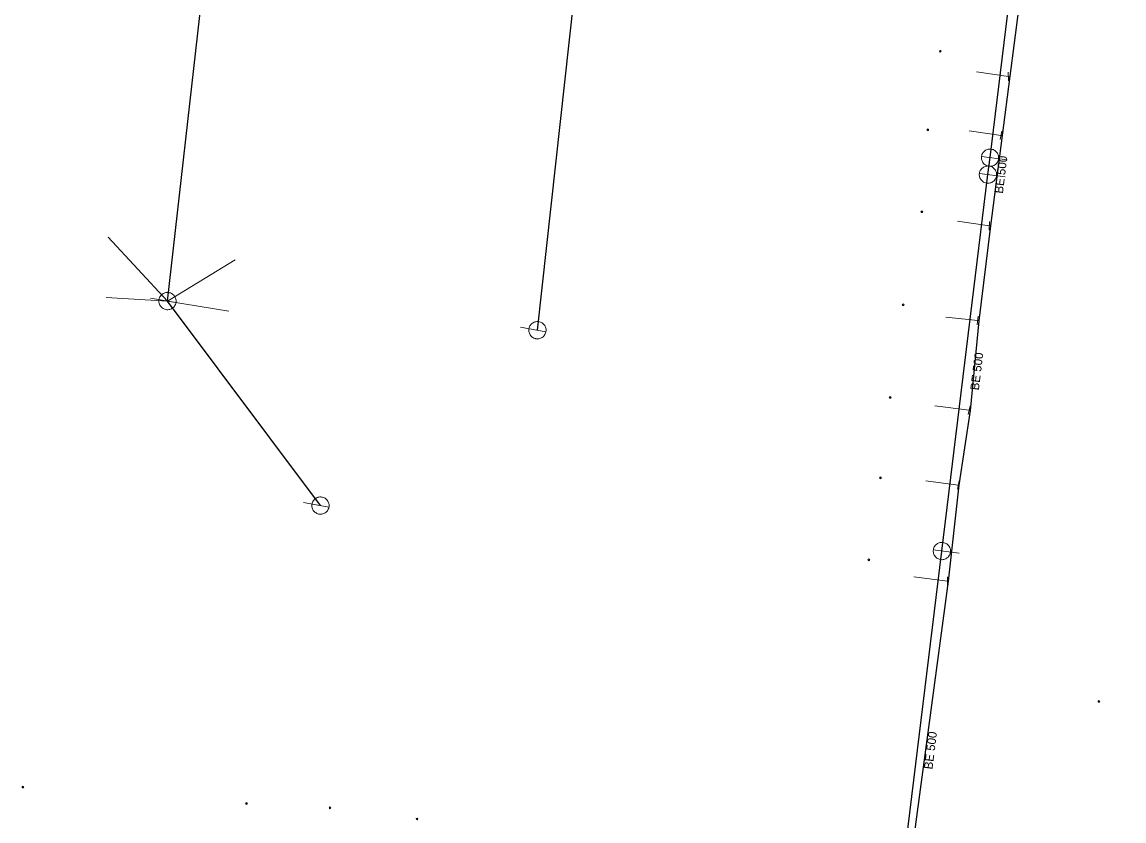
# Model space of a CAD drawing. Extents: x -783064 to -782702, y -1007904 to -1007145.
# Drawn here: x -783031.4 to -782903.8, y -1007381.8 to -1007289.3 of the extents above; entities that cross this region are included whole.
import ezdxf

# ---------------------------------------------------------------- set-up
doc = ezdxf.new("R2010")
doc.units = 0
doc.header["$LTSCALE"] = 0.4
doc.header["$PDMODE"] = 32
doc.header["$PDSIZE"] = 0.2
for name, color, linetype, lineweight in [('1', 7, 'Continuous', 13), ('11', 7, 'Continuous', 13), ('13', 7, 'Continuous', 13), ('14', 7, 'Continuous', 13), ('17', 7, 'Continuous', 25), ('22', 7, 'Continuous', 13), ('34', 7, 'Continuous', 13)]:
    doc.layers.add(name, color=color, linetype=linetype, lineweight=lineweight)

msp = doc.modelspace()

# ---------------------------------------------------------------- linework, layer by layer
at = {"layer": '1'}
for p in [(-782925.07, -1007292.719), (-782926.52, -1007301.809), (-782927.21, -1007311.299), (-782929.37, -1007322.069), (-782930.87, -1007332.779), (-782932, -1007342.089), (-782933.34, -1007351.579), (-782906.71, -1007367.969), (-783031.28, -1007377.879), (-783005.399, -1007379.789), (-782995.73, -1007380.279), (-782985.649, -1007381.569)]:
    msp.add_point(p, dxfattribs=at)
at = {"layer": '11'}
for p in [(-783021.414, -1007314.23), (-783006.703, -1007316.876), (-783021.626, -1007321.215), (-783007.444, -1007322.803)]:
    msp.add_line(p, (-783014.539, -1007321.63), dxfattribs=at)
at = {"layer": '13'}
for p, q in [((-782917.189, -1007295.627), (-782920.873, -1007295.112)), ((-782918.041, -1007302.452), (-782921.736, -1007301.928)), ((-782919.383, -1007312.937), (-782923.063, -1007312.385)), ((-782920.741, -1007323.879), (-782924.447, -1007323.499)), ((-782921.74, -1007334.257), (-782925.692, -1007333.773)), ((-782922.984, -1007342.927), (-782926.734, -1007342.418)), ((-782924.232, -1007354.049), (-782928.138, -1007353.554))]:
    msp.add_line(p, q, dxfattribs=at)
at = {"layer": '14', "lineweight": 25}
for p, q in [((-783014.539, -1007321.63), (-783008.89, -1007271.46)), ((-782971.71, -1007325), (-782966.579, -1007278.49)), ((-782996.829, -1007345.3), (-783014.539, -1007321.63))]:
    msp.add_line(p, q, dxfattribs=at)
at = {"layer": '14'}
for p, q in [((-782916.995, -1007295.62), (-782917.189, -1007295.627)), ((-782917.886, -1007302.487), (-782918.041, -1007302.452)), ((-782919.227, -1007312.942), (-782919.383, -1007312.937)), ((-782920.563, -1007323.904), (-782920.741, -1007323.879)), ((-782921.559, -1007334.301), (-782921.74, -1007334.257)), ((-782922.885, -1007342.946), (-782922.984, -1007342.927)), ((-782924.139, -1007354.049), (-782924.232, -1007354.049))]:
    msp.add_line(p, q, dxfattribs=at)
at = {"layer": '14', "lineweight": 25}
msp.add_lwpolyline([(-782930.292, -1007394.745), (-782924.885, -1007350.562), (-782919.554, -1007306.995), (-782919.314, -1007305.034), (-782912.27, -1007247.465)], dxfattribs=at)
at = {"layer": '17'}
msp.add_lwpolyline([(-782929.875, -1007401.245), (-782929.734, -1007399.601), (-782930.517, -1007396.682), (-782929.522, -1007392.415), (-782928.77, -1007388.515), (-782924.138, -1007354.049), (-782922.885, -1007342.946), (-782921.559, -1007334.301), (-782920.563, -1007323.904), (-782919.227, -1007312.942), (-782917.886, -1007302.487), (-782916.995, -1007295.62), (-782915.969, -1007287.894), (-782914.642, -1007276.256), (-782913.715, -1007269.301), (-782912.373, -1007257.698), (-782911.614, -1007250.289), (-782910.5, -1007239.254), (-782909.879, -1007233.809), (-782906.177, -1007206.061), (-782905.546, -1007203.154), (-782904.197, -1007194.592), (-782903.806, -1007194.072)], dxfattribs=at)
at = {"layer": '22'}
for p, q in [((-782917.328, -1007305.277), (-782920.306, -1007304.912)), ((-782917.568, -1007307.237), (-782920.546, -1007306.873)), ((-783016.509, -1007321.282), (-783013.554, -1007321.803)), ((-782973.68, -1007324.652), (-782970.725, -1007325.173)), ((-782998.799, -1007344.952), (-782995.844, -1007345.473)), ((-782922.899, -1007350.804), (-782925.877, -1007350.44))]:
    msp.add_line(p, q, dxfattribs=at)
for points in [[(-782919.192, -1007304.041), (-782919.3, -1007304.034), (-782919.41, -1007304.038), (-782919.519, -1007304.055), (-782919.624, -1007304.083), (-782919.726, -1007304.123), (-782919.823, -1007304.173), (-782919.914, -1007304.235), (-782919.998, -1007304.305), (-782920.074, -1007304.384), (-782920.14, -1007304.471), (-782920.197, -1007304.565), (-782920.242, -1007304.665), (-782920.277, -1007304.769), (-782920.3, -1007304.875), (-782920.311, -1007304.985), (-782920.311, -1007305.094), (-782920.299, -1007305.203), (-782920.275, -1007305.31), (-782920.238, -1007305.413), (-782920.192, -1007305.511), (-782920.134, -1007305.605), (-782920.066, -1007305.691), (-782919.989, -1007305.77), (-782919.905, -1007305.84), (-782919.814, -1007305.899), (-782919.716, -1007305.948), (-782919.613, -1007305.987), (-782919.508, -1007306.014), (-782919.399, -1007306.03), (-782919.289, -1007306.033), (-782919.18, -1007306.025), (-782919.073, -1007306.004), (-782918.968, -1007305.972), (-782918.868, -1007305.929), (-782918.772, -1007305.874), (-782918.684, -1007305.811), (-782918.602, -1007305.737), (-782918.53, -1007305.655), (-782918.466, -1007305.566), (-782918.413, -1007305.47), (-782918.371, -1007305.369), (-782918.34, -1007305.264), (-782918.321, -1007305.156), (-782918.313, -1007305.047), (-782918.318, -1007304.938), (-782918.334, -1007304.83), (-782918.362, -1007304.724), (-782918.402, -1007304.621), (-782918.453, -1007304.524), (-782918.513, -1007304.433), (-782918.583, -1007304.349), (-782918.663, -1007304.274), (-782918.749, -1007304.207), (-782918.843, -1007304.151), (-782918.942, -1007304.105), (-782919.047, -1007304.07), (-782919.154, -1007304.047)], [(-782919.432, -1007306.002), (-782919.54, -1007305.995), (-782919.65, -1007305.999), (-782919.759, -1007306.016), (-782919.864, -1007306.044), (-782919.966, -1007306.084), (-782920.063, -1007306.134), (-782920.154, -1007306.196), (-782920.238, -1007306.266), (-782920.314, -1007306.345), (-782920.38, -1007306.432), (-782920.437, -1007306.526), (-782920.482, -1007306.626), (-782920.517, -1007306.73), (-782920.54, -1007306.837), (-782920.551, -1007306.946), (-782920.551, -1007307.055), (-782920.539, -1007307.164), (-782920.515, -1007307.271), (-782920.478, -1007307.374), (-782920.432, -1007307.472), (-782920.373, -1007307.566), (-782920.306, -1007307.652), (-782920.229, -1007307.731), (-782920.145, -1007307.801), (-782920.054, -1007307.86), (-782919.956, -1007307.909), (-782919.853, -1007307.948), (-782919.748, -1007307.975), (-782919.639, -1007307.991), (-782919.529, -1007307.994), (-782919.42, -1007307.986), (-782919.313, -1007307.965), (-782919.208, -1007307.933), (-782919.107, -1007307.89), (-782919.012, -1007307.835), (-782918.924, -1007307.772), (-782918.842, -1007307.698), (-782918.77, -1007307.616), (-782918.706, -1007307.527), (-782918.653, -1007307.431), (-782918.611, -1007307.33), (-782918.58, -1007307.225), (-782918.561, -1007307.117), (-782918.553, -1007307.008), (-782918.558, -1007306.899), (-782918.574, -1007306.791), (-782918.602, -1007306.685), (-782918.642, -1007306.582), (-782918.693, -1007306.485), (-782918.753, -1007306.394), (-782918.823, -1007306.31), (-782918.903, -1007306.235), (-782918.989, -1007306.168), (-782919.083, -1007306.112), (-782919.182, -1007306.066), (-782919.287, -1007306.031), (-782919.394, -1007306.008)], [(-783014.713, -1007322.614), (-783014.604, -1007322.627), (-783014.495, -1007322.628), (-783014.385, -1007322.617), (-783014.279, -1007322.595), (-783014.174, -1007322.561), (-783014.075, -1007322.515), (-783013.981, -1007322.459), (-783013.894, -1007322.393), (-783013.814, -1007322.318), (-783013.743, -1007322.235), (-783013.681, -1007322.144), (-783013.631, -1007322.046), (-783013.59, -1007321.945), (-783013.562, -1007321.839), (-783013.544, -1007321.731), (-783013.539, -1007321.622), (-783013.546, -1007321.512), (-783013.564, -1007321.404), (-783013.595, -1007321.299), (-783013.636, -1007321.199), (-783013.689, -1007321.102), (-783013.752, -1007321.013), (-783013.825, -1007320.93), (-783013.905, -1007320.856), (-783013.993, -1007320.791), (-783014.088, -1007320.737), (-783014.189, -1007320.693), (-783014.293, -1007320.66), (-783014.401, -1007320.639), (-783014.51, -1007320.63), (-783014.619, -1007320.632), (-783014.727, -1007320.648), (-783014.834, -1007320.674), (-783014.937, -1007320.711), (-783015.035, -1007320.761), (-783015.126, -1007320.82), (-783015.212, -1007320.889), (-783015.288, -1007320.967), (-783015.356, -1007321.053), (-783015.414, -1007321.146), (-783015.462, -1007321.244), (-783015.499, -1007321.347), (-783015.524, -1007321.455), (-783015.537, -1007321.563), (-783015.538, -1007321.673), (-783015.527, -1007321.781), (-783015.505, -1007321.889), (-783015.47, -1007321.993), (-783015.425, -1007322.093), (-783015.369, -1007322.187), (-783015.304, -1007322.274), (-783015.228, -1007322.354), (-783015.145, -1007322.425), (-783015.055, -1007322.486), (-783014.958, -1007322.537), (-783014.855, -1007322.578), (-783014.75, -1007322.607)], [(-782971.884, -1007325.984), (-782971.775, -1007325.997), (-782971.666, -1007325.998), (-782971.556, -1007325.987), (-782971.45, -1007325.965), (-782971.345, -1007325.931), (-782971.246, -1007325.885), (-782971.152, -1007325.829), (-782971.065, -1007325.763), (-782970.985, -1007325.688), (-782970.914, -1007325.605), (-782970.852, -1007325.514), (-782970.802, -1007325.416), (-782970.761, -1007325.315), (-782970.733, -1007325.209), (-782970.715, -1007325.101), (-782970.71, -1007324.992), (-782970.717, -1007324.882), (-782970.735, -1007324.774), (-782970.766, -1007324.669), (-782970.807, -1007324.569), (-782970.86, -1007324.472), (-782970.923, -1007324.383), (-782970.996, -1007324.3), (-782971.076, -1007324.226), (-782971.164, -1007324.161), (-782971.259, -1007324.107), (-782971.36, -1007324.063), (-782971.464, -1007324.03), (-782971.572, -1007324.009), (-782971.681, -1007324), (-782971.79, -1007324.002), (-782971.898, -1007324.018), (-782972.005, -1007324.044), (-782972.108, -1007324.081), (-782972.206, -1007324.131), (-782972.297, -1007324.19), (-782972.383, -1007324.259), (-782972.459, -1007324.337), (-782972.527, -1007324.423), (-782972.585, -1007324.516), (-782972.633, -1007324.614), (-782972.67, -1007324.717), (-782972.695, -1007324.825), (-782972.708, -1007324.933), (-782972.709, -1007325.043), (-782972.698, -1007325.151), (-782972.676, -1007325.259), (-782972.641, -1007325.363), (-782972.596, -1007325.463), (-782972.54, -1007325.557), (-782972.475, -1007325.644), (-782972.399, -1007325.724), (-782972.316, -1007325.795), (-782972.226, -1007325.856), (-782972.129, -1007325.907), (-782972.026, -1007325.948), (-782971.921, -1007325.977)], [(-782997.003, -1007346.284), (-782996.894, -1007346.297), (-782996.785, -1007346.298), (-782996.675, -1007346.287), (-782996.569, -1007346.265), (-782996.464, -1007346.231), (-782996.365, -1007346.185), (-782996.271, -1007346.129), (-782996.184, -1007346.063), (-782996.104, -1007345.988), (-782996.033, -1007345.905), (-782995.971, -1007345.814), (-782995.921, -1007345.716), (-782995.88, -1007345.615), (-782995.852, -1007345.509), (-782995.834, -1007345.401), (-782995.829, -1007345.292), (-782995.836, -1007345.182), (-782995.854, -1007345.074), (-782995.885, -1007344.969), (-782995.926, -1007344.869), (-782995.979, -1007344.772), (-782996.042, -1007344.683), (-782996.115, -1007344.6), (-782996.195, -1007344.526), (-782996.283, -1007344.461), (-782996.378, -1007344.407), (-782996.479, -1007344.363), (-782996.583, -1007344.33), (-782996.691, -1007344.309), (-782996.8, -1007344.3), (-782996.909, -1007344.302), (-782997.017, -1007344.318), (-782997.124, -1007344.344), (-782997.227, -1007344.381), (-782997.325, -1007344.431), (-782997.416, -1007344.49), (-782997.502, -1007344.559), (-782997.578, -1007344.637), (-782997.646, -1007344.723), (-782997.704, -1007344.816), (-782997.752, -1007344.914), (-782997.789, -1007345.017), (-782997.814, -1007345.125), (-782997.827, -1007345.233), (-782997.828, -1007345.343), (-782997.817, -1007345.451), (-782997.795, -1007345.559), (-782997.76, -1007345.663), (-782997.715, -1007345.763), (-782997.659, -1007345.857), (-782997.594, -1007345.944), (-782997.518, -1007346.024), (-782997.435, -1007346.095), (-782997.345, -1007346.156), (-782997.248, -1007346.207), (-782997.145, -1007346.248), (-782997.04, -1007346.277)], [(-782924.763, -1007349.569), (-782924.871, -1007349.562), (-782924.981, -1007349.566), (-782925.09, -1007349.583), (-782925.195, -1007349.611), (-782925.297, -1007349.651), (-782925.394, -1007349.701), (-782925.485, -1007349.763), (-782925.569, -1007349.833), (-782925.645, -1007349.912), (-782925.711, -1007349.999), (-782925.768, -1007350.093), (-782925.813, -1007350.193), (-782925.848, -1007350.297), (-782925.871, -1007350.404), (-782925.882, -1007350.513), (-782925.882, -1007350.622), (-782925.87, -1007350.731), (-782925.846, -1007350.838), (-782925.809, -1007350.941), (-782925.763, -1007351.039), (-782925.704, -1007351.133), (-782925.637, -1007351.219), (-782925.56, -1007351.298), (-782925.476, -1007351.368), (-782925.385, -1007351.427), (-782925.287, -1007351.476), (-782925.184, -1007351.515), (-782925.079, -1007351.542), (-782924.97, -1007351.558), (-782924.86, -1007351.561), (-782924.751, -1007351.553), (-782924.644, -1007351.532), (-782924.539, -1007351.5), (-782924.438, -1007351.457), (-782924.343, -1007351.402), (-782924.255, -1007351.339), (-782924.173, -1007351.265), (-782924.101, -1007351.183), (-782924.037, -1007351.094), (-782923.984, -1007350.998), (-782923.942, -1007350.897), (-782923.911, -1007350.792), (-782923.892, -1007350.684), (-782923.884, -1007350.575), (-782923.889, -1007350.466), (-782923.905, -1007350.358), (-782923.933, -1007350.252), (-782923.973, -1007350.149), (-782924.024, -1007350.052), (-782924.084, -1007349.961), (-782924.154, -1007349.877), (-782924.234, -1007349.802), (-782924.32, -1007349.735), (-782924.414, -1007349.679), (-782924.513, -1007349.633), (-782924.618, -1007349.598), (-782924.725, -1007349.575)]]:
    msp.add_lwpolyline(points, close=True, dxfattribs=at)
at = {"layer": '34'}
for p, q in [((-782917.21, -1007295.127), (-782917.168, -1007296.126)), ((-782917.935, -1007301.963), (-782918.147, -1007302.94)), ((-782919.37, -1007312.437), (-782919.396, -1007313.436)), ((-782920.675, -1007323.383), (-782920.807, -1007324.374)), ((-782921.625, -1007333.77), (-782921.855, -1007334.743)), ((-782922.895, -1007342.434), (-782923.073, -1007343.419)), ((-782924.232, -1007353.549), (-782924.232, -1007354.549))]:
    msp.add_line(p, q, dxfattribs=at)

# ---------------------------------------------------------------- texts
at = {"layer": '1'}
for p in [(-782917.828, -1007309.233), (-782920.613, -1007331.997), (-782925.982, -1007375.872)]:
    msp.add_text('BE 500', height=1, rotation=83, dxfattribs=at).set_placement(p)

doc.saveas('drawing.dxf')
